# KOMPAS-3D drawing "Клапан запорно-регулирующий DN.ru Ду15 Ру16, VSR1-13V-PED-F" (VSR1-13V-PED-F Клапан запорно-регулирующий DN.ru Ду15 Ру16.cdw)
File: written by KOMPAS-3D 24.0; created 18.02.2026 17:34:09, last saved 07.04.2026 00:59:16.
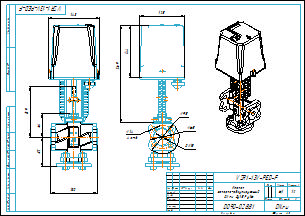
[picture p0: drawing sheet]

Document properties: Автор: R2D2; Форматы листов документа: A3; Полное имя файла: VSR1-13V-PED-F Клапан запорно-регулирующий DN.ru Ду15 Ру16.m3d; Масса: 6.1; Наименование: Клапан запорно-регулирующий DN.ru Ду15 Ру16; Количество листов документа: 1; Примечание: D090-02881

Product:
- Part/product: Клапан запорно-регулирующий DN.ru Ду15 Ру16  | designation VSR1-13V-PED-F
    Масса: 6.1
    Раздел спецификации: Прочие изделия
    Форматы листов документа: A3
    Примечание: D090-02881

Views: Вид 1, Спереди
Referenced files in E:\Работа\Зайцев\Солянка\VSR1-13V-PED-F Клапан запорно-регулирующий DN.ru\DN15\DN15 Kv0.16\: VSR1-13V-PED-F Клапан запорно-регулирующий DN.ru Ду15 Ру16.m3d
Referenced files in E:\Работа\Зайцев\Для компаса\: чертеж DN.ru А3.cdt
Referenced files in E:\Работа\Зайцев\Солянка\VSR1-13V-PED-F Клапан запорно-регулирующий DN.ru\DN15\DN15 Kv0.4\: VSR1-13V-PED-F Клапан запорно-регулирующий DN.ru Ду15 Ру16.m3d
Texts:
  Линейный размер
  VSR1-13V-PED-F
  чертеж DN.ru А3.cdt
  Клапан
  запорно-регулирующий
  DN.ru Ду15 Ру16
  Клапан запорно-регулирующий DN.ru Ду15 Ру16
  VSR1-13V-PED-F Клапан запорно-регулирующий DN.ru Ду15 Ру16
Dimensions and other numbers on the sheet: 0; 3; 2; 4; 130; 82; 143; 64; 139; 1:2; 1; 6,1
